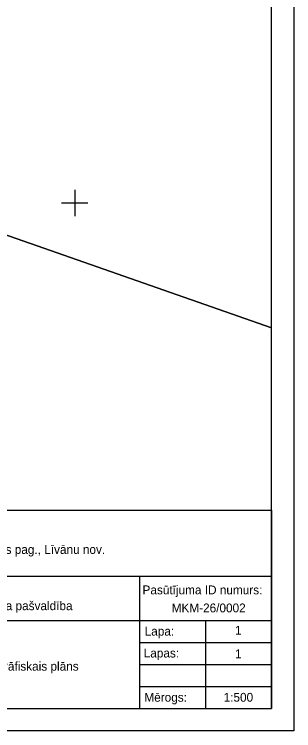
# Model space of a CAD drawing. Extents: x 635228 to 635525, y 248590 to 248800.
# Drawn here: x 635493.1 to 635524.8, y 248590.2 to 248671.4 of the extents above; entities that cross this region are included whole.
import ezdxf

# ---------------------------------------------------------------- set-up
doc = ezdxf.new("R2010")
doc.units = 0
for name, color, linetype in [('GEOD_ELEM_####_####_#', 7, 'Continuous'), ('RAMI_PLAN_####_TKST_#', 7, 'Continuous'), ('ROBZ_IERR_####_####_#', 7, 'Continuous'), ('ROBZ_UZMR_####_####_#', 7, 'Continuous')]:
    doc.layers.add(name, color=color, linetype=linetype)

msp = doc.modelspace()

# ---------------------------------------------------------------- linework, layer by layer
at = {"layer": 'GEOD_ELEM_####_####_#'}
for p, q in [((635500, 248651.5), (635500, 248650)), ((635498.5, 248650), (635500, 248650)), ((635500, 248650), (635500, 248648.5)), ((635500, 248650), (635501.5, 248650))]:
    msp.add_line(p, q, dxfattribs=at)
at = {"layer": 'RAMI_PLAN_####_TKST_#'}
for p, q in [((635432.337, 248615.176), (635522.337, 248615.176)), ((635522.337, 248615.176), (635522.337, 248592.676)), ((635479.837, 248607.676), (635522.337, 248607.676)), ((635507.337, 248607.676), (635507.337, 248592.676)), ((635432.337, 248602.676), (635522.337, 248602.676)), ((635507.337, 248602.676), (635522.337, 248602.676)), ((635514.837, 248602.676), (635514.837, 248592.676)), ((635507.337, 248600.176), (635522.337, 248600.176)), ((635507.337, 248597.676), (635522.337, 248597.676)), ((635507.337, 248595.176), (635522.337, 248595.176))]:
    msp.add_line(p, q, dxfattribs=at)
for points in [[(635227.837, 248590.176), (635227.837, 248800.176), (635524.837, 248800.176), (635524.837, 248590.176)], [(635237.837, 248797.676), (635237.837, 248592.676), (635522.337, 248592.676), (635522.337, 248797.676)]]:
    msp.add_lwpolyline(points, close=True, dxfattribs=at)
at = {"layer": 'ROBZ_IERR_####_####_#'}
msp.add_lwpolyline([(635522.337, 248635.854), (635430.959, 248667.773), (635424.543, 248670.014), (635439.457, 248681.038), (635465.459, 248707.539), (635482.561, 248729.828), (635498.129, 248747.855)], dxfattribs=at)
at = {"layer": 'ROBZ_UZMR_####_####_#'}
msp.add_lwpolyline([(635432.337, 248596.182), (635395.162, 248617.539), (635400.067, 248641.149), (635407.07, 248653.18), (635420.979, 248667.379), (635424.543, 248670.014), (635430.959, 248667.773), (635522.337, 248635.854)], dxfattribs=at)

# ---------------------------------------------------------------- texts
at = {"layer": 'RAMI_PLAN_####_TKST_#'}
for s, p in [('Līvas, Rožupes pag., Līvānu nov.', (635483.601, 248610.217)), ('Pasūtījuma ID numurs:', (635507.687, 248605.634)), ('Līvānu novada pašvaldība', (635484.134, 248603.837)), ('MKM-26/0002', (635510.991, 248603.589)), ('Lapa:', (635507.93, 248600.953)), ('1', (635518.174, 248601.057)), ('Lapas:', (635507.82, 248598.474)), ('1', (635518.174, 248598.391)), ('Topogrāfiskais plāns', (635488.176, 248596.979)), ('Mērogs:', (635507.898, 248593.459)), ('1:500', (635516.889, 248593.459))]:
    msp.add_text(s, height=1, dxfattribs=at).set_placement(p)

doc.saveas('drawing.dxf')
